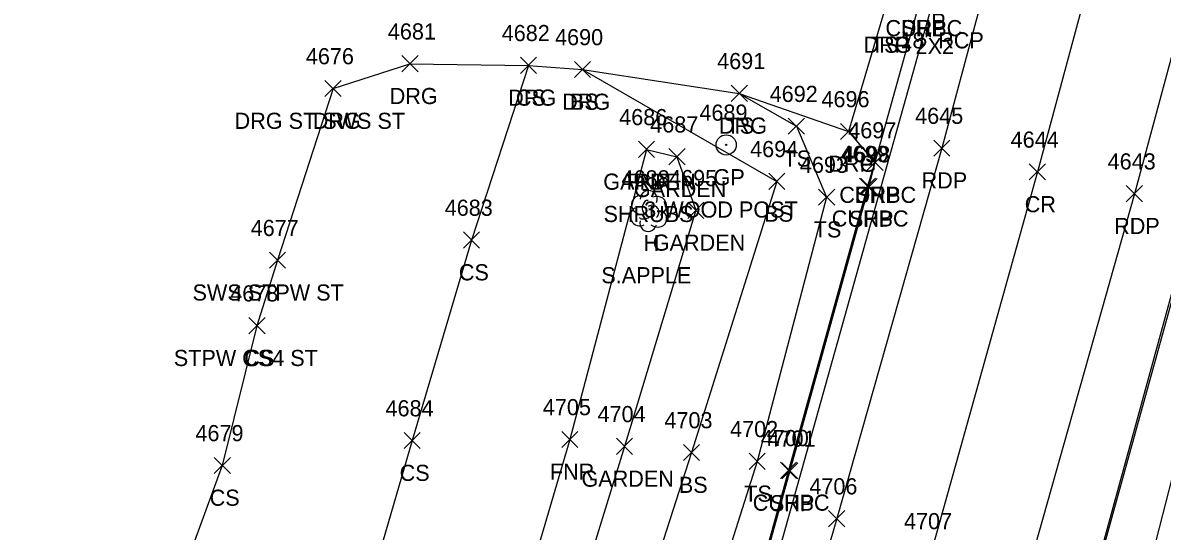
# Model space of a CAD drawing. Extents: x 1443912 to 1445411, y 621446 to 623693.
# Drawn here: x 1444769.4 to 1444910.4, y 623071.7 to 623134.7 of the extents above; entities that cross this region are included whole.
import ezdxf

# ---------------------------------------------------------------- set-up
doc = ezdxf.new("R2010")
doc.units = 0
for name, color, linetype in [('D_A', 7, 'Continuous'), ('D_C', 7, 'Continuous'), ('DCP', 7, 'Continuous'), ('L_A', 7, 'Continuous'), ('L_C', 7, 'Continuous'), ('L_I', 7, 'Continuous'), ('L_TIC', 7, 'Continuous'), ('LAPB', 7, 'Continuous'), ('LBF', 7, 'Continuous'), ('LELB', 7, 'Continuous'), ('LFNC', 7, 'Continuous'), ('LTD', 7, 'Continuous'), ('P_A', 7, 'Continuous'), ('P_I', 7, 'Continuous'), ('P_TIC', 7, 'Continuous'), ('PET', 7, 'Continuous'), ('PRC', 7, 'Continuous'), ('PSP', 7, 'Continuous'), ('R_A', 7, 'Continuous'), ('R_C', 7, 'Continuous'), ('R_I', 7, 'Continuous'), ('R_TIC', 7, 'Continuous'), ('RC', 7, 'Continuous'), ('RDG', 7, 'Continuous'), ('RDP', 7, 'Continuous'), ('RGP', 7, 'Continuous'), ('RSW', 7, 'Continuous')]:
    doc.layers.add(name, color=color, linetype=linetype)

msp = doc.modelspace()

# ---------------------------------------------------------------- linework, layer by layer
at = {"layer": 'DCP'}
msp.add_lwpolyline([(1444882.45, 623138.81), (1444832.84, 622961.57)], dxfattribs=at)
at = {"layer": 'L_TIC'}
for points in [[(1444830.97, 623128.38), (1444832.97, 623130.38)], [(1444832.97, 623128.38), (1444830.97, 623130.38)], [(1444837.66, 623127.87), (1444839.66, 623129.87)], [(1444839.66, 623127.87), (1444837.66, 623129.87)], [(1444857.07, 623124.91), (1444859.07, 623126.91)], [(1444859.07, 623124.91), (1444857.07, 623126.91)], [(1444864.13, 623120.84), (1444866.13, 623122.84)], [(1444866.13, 623120.84), (1444864.13, 623122.84)], [(1444845.57, 623117.97), (1444847.57, 623119.97)], [(1444847.57, 623117.97), (1444845.57, 623119.97)], [(1444845.57, 623117.97), (1444847.57, 623119.97)], [(1444847.57, 623117.97), (1444845.57, 623119.97)], [(1444849.35, 623117.06), (1444851.35, 623119.06)], [(1444851.35, 623117.06), (1444849.35, 623119.06)], [(1444861.71, 623114.01), (1444863.71, 623116.01)], [(1444863.71, 623114.01), (1444861.71, 623116.01)], [(1444867.88, 623112.06), (1444869.88, 623114.06)], [(1444869.88, 623112.06), (1444867.88, 623114.06)], [(1444851.69, 623110.42), (1444853.69, 623112.42)], [(1444853.69, 623110.42), (1444851.69, 623112.42)], [(1444823.91, 623106.74), (1444825.91, 623108.74)], [(1444825.91, 623106.74), (1444823.91, 623108.74)], [(1444799.89, 623104.24), (1444801.89, 623106.24)], [(1444801.89, 623104.24), (1444799.89, 623106.24)], [(1444797.36, 623096.13), (1444799.36, 623098.13)], [(1444799.36, 623096.13), (1444797.36, 623098.13)], [(1444797.36, 623096.13), (1444799.36, 623098.13)], [(1444799.36, 623096.13), (1444797.36, 623098.13)], [(1444816.58, 623081.9), (1444818.58, 623083.9)], [(1444818.58, 623081.9), (1444816.58, 623083.9)], [(1444836.09, 623082.04), (1444838.09, 623084.04)], [(1444838.09, 623082.04), (1444836.09, 623084.04)], [(1444842.86, 623081.18), (1444844.86, 623083.18)], [(1444844.86, 623081.18), (1444842.86, 623083.18)], [(1444851.14, 623080.42), (1444853.14, 623082.42)], [(1444853.14, 623080.42), (1444851.14, 623082.42)], [(1444793.06, 623078.82), (1444795.06, 623080.82)], [(1444795.06, 623078.82), (1444793.06, 623080.82)], [(1444859.27, 623079.32), (1444861.27, 623081.32)], [(1444861.27, 623079.32), (1444859.27, 623081.32)]]:
    msp.add_lwpolyline(points, dxfattribs=at)
at = {"layer": 'LAPB'}
msp.add_lwpolyline([(1444846.57, 623118.97), (1444850.35, 623118.06), (1444852.69, 623111.42), (1444843.86, 623082.18), (1444837.57, 623061.8), (1444830.36, 623060.15)], dxfattribs=at)
at = {"layer": 'LBF'}
msp.add_lwpolyline([(1444800.89, 623105.24), (1444798.36, 623097.13)], dxfattribs=at)
at = {"layer": 'LELB'}
for points in [[(1444965.39, 623126.71), (1444945.13, 623132.56), (1444929.57, 623133.35), (1444925.64, 623128.64), (1444923.13, 623120.2), (1444914.4, 623088.98), (1444907.7, 623062.92), (1444896.39, 623030.41), (1444888.48, 622997.96), (1444877.45, 622951.18), (1444886.07, 622942.7), (1444898.81, 622937.04), (1444925.54, 622926.46)], [(1444838.66, 623128.87), (1444862.71, 623115.01), (1444852.14, 623081.42), (1444841.44, 623048.05), (1444831.02, 623011.13), (1444817.95, 622967.27), (1444804.29, 622966.33), (1444773.86, 622973.18)], [(1444831.97, 623129.38), (1444824.91, 623107.74), (1444817.58, 623082.9), (1444810.01, 623056.94)], [(1444858.07, 623125.91), (1444865.13, 623121.84), (1444868.88, 623113.06), (1444860.27, 623080.32), (1444849.37, 623045.92), (1444839.15, 623009.44), (1444826.56, 622960.65), (1444815.44, 622958.72), (1444796.27, 622957.9), (1444763.62, 622963.41)], [(1444798.36, 623097.13), (1444794.06, 623079.82), (1444787.83, 623062.76)]]:
    msp.add_lwpolyline(points, dxfattribs=at)
at = {"layer": 'LFNC'}
msp.add_lwpolyline([(1444846.57, 623118.97), (1444837.09, 623083.04), (1444830.36, 623060.15)], dxfattribs=at)
at = {"layer": 'LTD'}
msp.add_line((1444846.8, 623111.38), (1444846.8, 623111.38), dxfattribs=at)
msp.add_line((1444846.8, 623111.38), (1444846.8, 623111.38), dxfattribs=at)
msp.add_arc((1444846.85, 623112.81), 1.05, 335.5272, 180.9563, dxfattribs=at)
for centre, major_axis, ratio, start_param, end_param in [((1444846.01, 623112.05), (1.21, -0.51), 0.895232, 1.570796, 4.712389), ((1444847.84, 623111.96), (-1.14, -0.48), 0.949671, 1.570796, 4.712389), ((1444845.72, 623110.67), (0.58, -1.04), 0.959034, 3.141593, 6.283185), ((1444846.59, 623111.84), (-0.208, -0.792), 0.645439, 3.141593, 6.283185), ((1444847.3, 623111.21), (-0.5, 0.667), 0.989748, 3.141593, 6.283185), ((1444846.34, 623110.63), (-0.625, -0.083), 0.423636, 0, 3.141593), ((1444847.8, 623110.55), (-1.09, 0.79), 0.841452, 1.570796, 4.712389), ((1444846.8, 623109.88), (0.26, 1.06), 0.942809, 1.570796, 4.712389)]:
    msp.add_ellipse(centre, major_axis=major_axis, ratio=ratio, start_param=start_param, end_param=end_param, dxfattribs=at)
at = {"layer": 'P_TIC'}
for points in [[(1444882.14, 623118.13), (1444884.14, 623120.13)], [(1444884.14, 623118.13), (1444882.14, 623120.13)], [(1444873.86, 623116.34), (1444875.86, 623118.34)], [(1444875.86, 623116.34), (1444873.86, 623118.34)], [(1444893.97, 623115.18), (1444895.97, 623117.18)], [(1444895.97, 623115.18), (1444893.97, 623117.18)], [(1444873.12, 623113.36), (1444875.12, 623115.36)], [(1444875.12, 623113.36), (1444873.12, 623115.36)], [(1444905.98, 623112.48), (1444907.98, 623114.48)], [(1444907.98, 623112.48), (1444905.98, 623114.48)], [(1444863.33, 623078.14), (1444865.33, 623080.14)], [(1444865.33, 623078.14), (1444863.33, 623080.14)], [(1444869.13, 623072.23), (1444871.13, 623074.23)], [(1444871.13, 623072.23), (1444869.13, 623074.23)]]:
    msp.add_lwpolyline(points, dxfattribs=at)
at = {"layer": 'PET'}
for points in [[(1445036.7, 623677.7), (1445026.38, 623639.78), (1445008.65, 623576.15), (1444996.95, 623532.89), (1444979.78, 623472.47), (1444964.83, 623416.22), (1444955.71, 623382.54), (1444949.17, 623358.13), (1444939.29, 623323.43), (1444926.27, 623275.91), (1444914.83, 623235.04), (1444901.53, 623186.46), (1444892.14, 623152.69), (1444883.14, 623119.13), (1444870.13, 623073.23), (1444861.49, 623043.31), (1444850.84, 623006.82), (1444834.61, 622954.83), (1444817.28, 622898.33)], [(1445060.04, 623670.52), (1445049.49, 623631.42), (1445031.61, 623567.44), (1445020.44, 623527.05), (1445003.5, 623465.59), (1444988.1, 623409.14), (1444976.63, 623367.03), (1444962.49, 623315.05), (1444949.49, 623267.35), (1444937.78, 623225.39), (1444926.09, 623182.22), (1444915.48, 623145.05), (1444906.98, 623113.48), (1444893.64, 623066.1), (1444886.06, 623037.31), (1444876.58, 623001.08), (1444863.33, 622947.05), (1444849.43, 622890.74)]]:
    msp.add_lwpolyline(points, dxfattribs=at)
at = {"layer": 'PRC'}
msp.add_lwpolyline([(1445048.12, 623674.07), (1445038.05, 623635.88), (1445020.14, 623572.7), (1445008.5, 623529.11), (1444991.68, 623469.75), (1444976.21, 623412.44), (1444964.87, 623369.69), (1444950.64, 623318.47), (1444938.05, 623272.58), (1444925.39, 623227.3), (1444913.85, 623184.57), (1444903.74, 623148.67), (1444894.97, 623116.18), (1444881.8, 623068.92), (1444873.97, 623040.25), (1444864.1, 623005.34), (1444846.73, 622950.74), (1444829.37, 622896.11)], dxfattribs=at)
at = {"layer": 'PSP'}
for points in [[(1444984.52, 623364.95), (1444970.17, 623313), (1444960.84, 623279.61), (1444959.91, 623275.87), (1444955.54, 623257.94), (1444945.5, 623223.6), (1444933.94, 623181.42), (1444927.82, 623159.66), (1444926.96, 623156.44), (1444922.1, 623137.71), (1444921.08, 623134.92), (1444914.5, 623111.78), (1444901.39, 623063.86), (1444892.12, 623031.22), (1444883.17, 622999.19), (1444870.02, 622952.2), (1444868.68, 622947.27), (1444864.21, 622931.67)], [(1444938.45, 623347.36), (1444929.03, 623313.43), (1444928.24, 623309.81), (1444922.87, 623290.92), (1444911.87, 623250.74), (1444910.83, 623246.92), (1444910.34, 623244.45), (1444906.24, 623231), (1444905.23, 623226.67), (1444898.9, 623204.12), (1444894.62, 623188.31), (1444891.5, 623176.9), (1444890.54, 623173.34), (1444886.06, 623157.56), (1444885.11, 623153.68), (1444881.77, 623141.71), (1444880.57, 623137.99), (1444874.86, 623117.34), (1444874.12, 623114.36), (1444864.33, 623079.14), (1444854.72, 623044.47)]]:
    msp.add_lwpolyline(points, dxfattribs=at)
at = {"layer": 'R_TIC'}
for points in [[(1444816.3, 623128.58), (1444818.3, 623130.58)], [(1444818.3, 623128.58), (1444816.3, 623130.58)], [(1444830.97, 623128.38), (1444832.97, 623130.38)], [(1444832.97, 623128.38), (1444830.97, 623130.38)], [(1444837.66, 623127.87), (1444839.66, 623129.87)], [(1444839.66, 623127.87), (1444837.66, 623129.87)], [(1444806.77, 623125.51), (1444808.77, 623127.51)], [(1444808.77, 623125.51), (1444806.77, 623127.51)], [(1444806.77, 623125.51), (1444808.77, 623127.51)], [(1444808.77, 623125.51), (1444806.77, 623127.51)], [(1444857.07, 623124.91), (1444859.07, 623126.91)], [(1444859.07, 623124.91), (1444857.07, 623126.91)], [(1444870.6, 623120.19), (1444872.6, 623122.19)], [(1444872.6, 623120.19), (1444870.6, 623122.19)], [(1444870.6, 623120.19), (1444872.6, 623122.19)], [(1444872.6, 623120.19), (1444870.6, 623122.19)], [(1444873.86, 623116.34), (1444875.86, 623118.34)], [(1444875.86, 623116.34), (1444873.86, 623118.34)], [(1444873.86, 623116.34), (1444875.86, 623118.34)], [(1444875.86, 623116.34), (1444873.86, 623118.34)], [(1444872.93, 623113.41), (1444874.93, 623115.41)], [(1444874.93, 623113.41), (1444872.93, 623115.41)], [(1444799.89, 623104.24), (1444801.89, 623106.24)], [(1444801.89, 623104.24), (1444799.89, 623106.24)], [(1444863.15, 623078.21), (1444865.15, 623080.21)], [(1444865.15, 623078.21), (1444863.15, 623080.21)]]:
    msp.add_lwpolyline(points, dxfattribs=at)
at = {"layer": 'RC'}
for points in [[(1444922.1, 623137.71), (1444921.21, 623134.74), (1444914.79, 623111.77), (1444901.49, 623063.72), (1444892.45, 623031.11), (1444883.39, 622999.32), (1444870.3, 622952.19), (1444868.68, 622947.27)], [(1444874.86, 623117.34), (1444873.93, 623114.41), (1444864.15, 623079.21), (1444854.57, 623044.55), (1444844.4, 623008.1), (1444831.55, 622962.48), (1444830.72, 622958.68)]]:
    msp.add_lwpolyline(points, dxfattribs=at)
at = {"layer": 'RDG'}
msp.add_lwpolyline([(1444807.77, 623126.51), (1444817.3, 623129.58), (1444831.97, 623129.38), (1444838.66, 623128.87), (1444858.07, 623125.91), (1444871.6, 623121.19)], dxfattribs=at)
at = {"layer": 'RDP'}
msp.add_lwpolyline([(1444880.57, 623137.99), (1444875.95, 623135.93), (1444871.6, 623121.19), (1444874.86, 623117.34)], dxfattribs=at)
at = {"layer": 'RGP'}
msp.add_line((1444856.44, 623119.52), (1444856.44, 623119.52), dxfattribs=at)
for radius in [1.25, 0.0833]:
    msp.add_circle((1444856.44, 623119.52), radius, dxfattribs=at)
at = {"layer": 'RSW'}
msp.add_lwpolyline([(1444807.77, 623126.51), (1444800.89, 623105.24)], dxfattribs=at)

# ---------------------------------------------------------------- texts
at = {"layer": 'D_A'}
msp.add_text('P', height=2, dxfattribs=at).set_placement((1444881.83, 623133.81))
at = {"layer": 'D_C'}
for s, p in [('18" RCP', (1444878.02, 623131.48)), ('2X2', (1444879.89, 623130.78))]:
    msp.add_text(s, height=2, dxfattribs=at).set_placement(p)
at = {"layer": 'L_A'}
for s, p in [('TS', (1444874.36, 623130.93)), ('CS', (1444830.41, 623124.38)), ('BS', (1444837.1, 623123.87)), ('TS', (1444856.48, 623120.91)), ('TS', (1444863.54, 623116.84)), ('GARDEN', (1444841.23, 623113.97)), ('FNR', (1444844.1, 623113.97)), ('GARDEN', (1444845.02, 623113.06)), ('BS', (1444861.16, 623110.01)), ('TS', (1444867.29, 623108.06)), ('H', (1444846.23, 623106.38)), ('GARDEN', (1444847.36, 623106.42)), ('CS', (1444823.35, 623102.74)), ('SWS STPW ST', (1444790.38, 623100.24)), ('STPW CS4 ST', (1444788.06, 623092.13)), ('CS', (1444796.8, 623092.13)), ('CS', (1444816.02, 623077.9)), ('FNR', (1444834.62, 623078.04)), ('GARDEN', (1444838.53, 623077.18)), ('BS', (1444850.58, 623076.42)), ('CS', (1444792.5, 623074.82)), ('TS', (1444858.68, 623075.32))]:
    msp.add_text(s, height=2, dxfattribs=at).set_placement(p)
at = {"layer": 'L_C'}
for s, p in [('SHRUBS', (1444841.26, 623109.97)), ('S.APPLE', (1444840.99, 623102.38))]:
    msp.add_text(s, height=2, dxfattribs=at).set_placement(p)
at = {"layer": 'L_I'}
for s, p in [('4682', (1444828.66, 623132.38)), ('4690', (1444835.26, 623131.87)), ('4691', (1444855.33, 623128.91)), ('4692', (1444861.83, 623124.84)), ('4686', (1444843.2, 623121.97)), ('4686', (1444843.2, 623121.97)), ('4687', (1444847.04, 623121.06)), ('4694', (1444859.41, 623118.01)), ('4693', (1444865.57, 623116.06)), ('4688', (1444843.49, 623114.38)), ('4695', (1444849.38, 623114.42)), ('4683', (1444821.6, 623110.74)), ('4677', (1444797.58, 623108.24)), ('4678', (1444795.05, 623100.13)), ('4678', (1444795.05, 623100.13)), ('4684', (1444814.27, 623085.9)), ('4705', (1444833.75, 623086.04)), ('4704', (1444840.52, 623085.18)), ('4703', (1444848.8, 623084.42)), ('4679', (1444790.74, 623082.82)), ('4702', (1444856.93, 623083.32))]:
    msp.add_text(s, height=2, dxfattribs=at).set_placement(p)
at = {"layer": 'P_A'}
for s, p in [('SHP', (1444878.11, 623132.99)), ('RDP', (1444880.63, 623114.13)), ('SHP', (1444872.4, 623112.34)), ('CR', (1444893.4, 623111.18)), ('SHP', (1444871.65, 623109.36)), ('RDP', (1444904.47, 623108.48)), ('SHP', (1444861.86, 623074.14))]:
    msp.add_text(s, height=2, dxfattribs=at).set_placement(p)
at = {"layer": 'P_I'}
for s, p in [('4645', (1444879.84, 623122.13)), ('4697', (1444871.56, 623120.34)), ('4644', (1444891.66, 623119.18)), ('4698', (1444870.81, 623117.36)), ('4643', (1444903.67, 623116.48)), ('4701', (1444861.56, 623082.14)), ('4706', (1444866.74, 623076.23)), ('4707', (1444878.46, 623071.92))]:
    msp.add_text(s, height=2, dxfattribs=at).set_placement(p)
at = {"layer": 'R_A'}
for s, p in [('CURBC', (1444876.16, 623132.99)), ('DRP', (1444878.06, 623132.99)), ('DRG', (1444873.44, 623130.93)), ('DRP', (1444873.44, 623130.93)), ('DRG', (1444814.79, 623124.58)), ('DRG', (1444829.46, 623124.38)), ('DRG', (1444836.14, 623123.87)), ('DRG ST SWS ST', (1444795.59, 623121.51)), ('DRG', (1444805.26, 623121.51)), ('DRG', (1444855.56, 623120.91)), ('DRG', (1444869.09, 623116.19)), ('DRP', (1444869.09, 623116.19)), ('GP', (1444854.88, 623114.52)), ('CURBC', (1444870.45, 623112.34)), ('DRP', (1444872.35, 623112.34)), ('CURBC', (1444869.51, 623109.41)), ('SWS STPW ST', (1444790.38, 623100.24)), ('CURBC', (1444859.73, 623074.21))]:
    msp.add_text(s, height=2, dxfattribs=at).set_placement(p)
at = {"layer": 'R_C'}
msp.add_text('3-WOOD POST', height=2, dxfattribs=at).set_placement((1444846.29, 623110.52))
at = {"layer": 'R_I'}
for s, p in [('4681', (1444814.56, 623132.58)), ('4682', (1444828.66, 623132.38)), ('4690', (1444835.26, 623131.87)), ('4676', (1444804.41, 623129.51)), ('4676', (1444804.41, 623129.51)), ('4691', (1444855.33, 623128.91)), ('4696', (1444868.24, 623124.19)), ('4696', (1444868.24, 623124.19)), ('4689', (1444853.13, 623122.52)), ('4697', (1444871.56, 623120.34)), ('4697', (1444871.56, 623120.34)), ('4699', (1444870.61, 623117.41)), ('4677', (1444797.58, 623108.24)), ('4700', (1444860.72, 623082.21))]:
    msp.add_text(s, height=2, dxfattribs=at).set_placement(p)

doc.saveas('drawing.dxf')
